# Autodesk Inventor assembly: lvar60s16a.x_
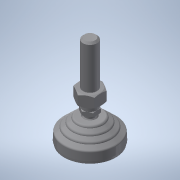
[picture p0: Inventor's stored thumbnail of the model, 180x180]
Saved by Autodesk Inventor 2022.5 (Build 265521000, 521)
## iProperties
Part Number: lvar60s16a.x_
Material: 一般
Document SubType Name: Assembly
Designer: ImaoCorp
Sending System: SOLIDWORKS 2017-2017317
MC: AMD64
MC_MODEL: Intel64 Family 6 Model 60 Stepping 3, GenuineIntel
OS: Windows_NT
FRU: Parasolid Version 29.0, build 201,  4-17-2017
FORMAT: text
GUISE: transmit
KEY: lvar60s16a
FILE: lvar60s16a.x_t
DATE: Mon Jul 01 18:13:06 2019
Author: ImaoCorp
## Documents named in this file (3)
- X:\14_SW2022-Inv2022\00_全2023-1023新製品(TCC)まで\l\lvar60s16a\LVAR60S16A.iam
- X:\14_SW2022-Inv2022\00_全2023-1023新製品(TCC)まで\l\lvar60s16a\lvar60s16a_01.ipt
- X:\14_SW2022-Inv2022\00_全2023-1023新製品(TCC)まで\l\lvar60s16a\lvar60s16a_02.ipt
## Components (2 placed, 2 different names)
1. lvar60s16a_01
2. lvar60s16a_02
